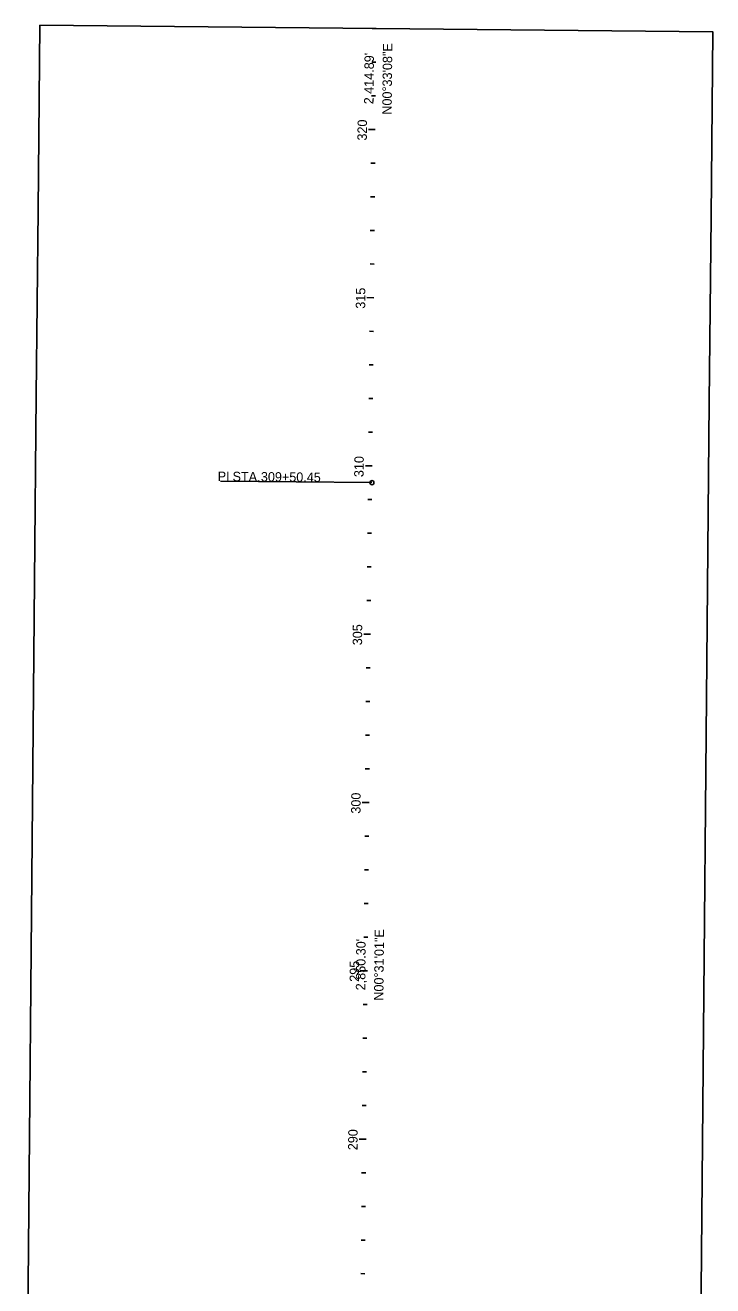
# Model space of a CAD drawing. Extents: x 1807668 to 1809726, y 297763 to 325145.
# Drawn here: x 1807683 to 1809726, y 309133 to 312879 of the extents above; entities that cross this region are included whole.
import ezdxf

# ---------------------------------------------------------------- set-up
doc = ezdxf.new("R2010")
doc.units = 0
for name, color, linetype in [('GE_P_Alignment_500_Bearings', 7, 'Continuous'), ('GE_P_Alignment_500_Cardinal_Points', 7, 'Continuous'), ('GE_P_Alignment_500_Distances', 7, 'Continuous'), ('GE_P_Alignment_500_Stations', 7, 'Continuous'), ('SH_Named_Boundary', 7, 'Continuous')]:
    doc.layers.add(name, color=color, linetype=linetype)

msp = doc.modelspace()

# ---------------------------------------------------------------- linework, layer by layer
at = {"layer": 'GE_P_Alignment_500_Cardinal_Points'}
msp.add_line((1808713.2, 311519.5), (1808263.2, 311523.9), dxfattribs=at)
msp.add_circle((1808713.2, 311519.5), 6, dxfattribs=at)
at = {"layer": 'GE_P_Alignment_500_Stations'}
for p, q in [((1808726.2, 312869), (1808714.2, 312869.1)), ((1808725.3, 312769), (1808713.3, 312769.1)), ((1808724.3, 312669), (1808712.3, 312669.1)), ((1808723.3, 312569), (1808703.3, 312569.2)), ((1808722.4, 312469), (1808710.4, 312469.2)), ((1808721.4, 312369), (1808709.4, 312369.2)), ((1808720.4, 312269), (1808708.4, 312269.2)), ((1808719.5, 312169), (1808707.5, 312169.2)), ((1808718.5, 312069.1), (1808698.5, 312069.2)), ((1808717.5, 311969.1), (1808705.5, 311969.2)), ((1808716.6, 311869.1), (1808704.6, 311869.2)), ((1808715.6, 311769.1), (1808703.6, 311769.2)), ((1808714.7, 311669.1), (1808702.7, 311669.2)), ((1808713.7, 311569.1), (1808693.7, 311569.3)), ((1808712.8, 311469.1), (1808700.8, 311469.2)), ((1808711.9, 311369.1), (1808699.9, 311369.2)), ((1808711, 311269.1), (1808699, 311269.2)), ((1808710.1, 311169.1), (1808698.1, 311169.2)), ((1808709.2, 311069.1), (1808689.2, 311069.3)), ((1808708.2, 310969.1), (1808696.2, 310969.2)), ((1808707.3, 310869.1), (1808695.3, 310869.2)), ((1808706.4, 310769.1), (1808694.4, 310769.2)), ((1808705.5, 310669.1), (1808693.5, 310669.2)), ((1808704.6, 310569.1), (1808684.6, 310569.3)), ((1808703.7, 310469.1), (1808691.7, 310469.2)), ((1808702.8, 310369.1), (1808690.8, 310369.2)), ((1808701.9, 310269.1), (1808689.9, 310269.2)), ((1808701, 310169.1), (1808689, 310169.2)), ((1808700.1, 310069.1), (1808680.1, 310069.3)), ((1808699.2, 309969.1), (1808687.2, 309969.3)), ((1808698.3, 309869.1), (1808686.3, 309869.3)), ((1808697.4, 309769.2), (1808685.4, 309769.3)), ((1808696.5, 309669.2), (1808684.5, 309669.3)), ((1808695.6, 309569.2), (1808675.6, 309569.3)), ((1808694.7, 309469.2), (1808682.7, 309469.3)), ((1808693.8, 309369.2), (1808681.8, 309369.3)), ((1808692.9, 309269.2), (1808680.9, 309269.3)), ((1808692, 309169.2), (1808680, 309169.3))]:
    msp.add_line(p, q, dxfattribs=at)
at = {"layer": 'SH_Named_Boundary'}
msp.add_lwpolyline([(1807682.8, 307372.8), (1809682.8, 307365.6), (1809684.8, 307915.6), (1809686.8, 308465.6), (1809690.6, 309010.2), (1809695.6, 309560.1), (1809700.5, 310110.1), (1809705.5, 310660.1), (1809710.5, 311210.1), (1809715.6, 311759.4), (1809720.9, 312309.4), (1809726.2, 312859.4), (1807726.3, 312878.7), (1807721, 312328.7), (1807715.7, 311778.7), (1807710.5, 311228.1), (1807705.6, 310678.1), (1807700.6, 310128.2), (1807695.7, 309578.2), (1807690.7, 309028.2), (1807686.8, 308472.8), (1807684.8, 307922.8)], close=True, dxfattribs=at)

# ---------------------------------------------------------------- texts
at = {"layer": 'GE_P_Alignment_500_Bearings'}
for s, rotation, p in [('N00°33\'08"E', 89.4478, (1808771.8, 312612.8)), ('N00°31\'01"E', 89.4832, (1808747.3, 309980.4))]:
    msp.add_text(s, height=28, rotation=rotation, dxfattribs=at).set_placement(p)
at = {"layer": 'GE_P_Alignment_500_Cardinal_Points'}
for s, p in [('PI', (1808254.7, 311524.4)), (' STA. ', (1808288.6, 311524)), ('309+50.45', (1808383.1, 311523.1))]:
    msp.add_text(s, height=28, rotation=359.4478, dxfattribs=at).set_placement(p)
at = {"layer": 'GE_P_Alignment_500_Distances'}
for s, rotation, p in [("2,414.89'", 89.4478, (1808717.8, 312643.5)), ("2,850.30'", 89.4832, (1808693.4, 310011))]:
    msp.add_text(s, height=28, rotation=rotation, dxfattribs=at).set_placement(p)
at = {"layer": 'GE_P_Alignment_500_Stations'}
for s, rotation, p in [('320', 89.4478, (1808698, 312535.8)), ('315', 89.4478, (1808693.2, 312036.2)), ('310', 89.4478, (1808688.4, 311535.9)), ('305', 89.4832, (1808683.9, 311036.3)), ('300', 89.4832, (1808679.3, 310535.9)), ('295', 89.4832, (1808674.8, 310036.3)), ('290', 89.4832, (1808670.3, 309535.9))]:
    msp.add_text(s, height=28, rotation=rotation, dxfattribs=at).set_placement(p)

doc.saveas('drawing.dxf')
